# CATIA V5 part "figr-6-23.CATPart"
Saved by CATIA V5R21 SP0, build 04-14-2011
Part number: Part1
Bounding box of the stored display mesh (mm): x 0 to 150, y -70 to 70, z -150 to 69.968
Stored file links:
  D:\CATIA V5R21 E-RESOURCES\CATIA-V5R21\catia-v5r21-prt\c06-catia-v5r21-prt\c06-catia-v5r21-figr-6-23.CATPart
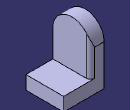
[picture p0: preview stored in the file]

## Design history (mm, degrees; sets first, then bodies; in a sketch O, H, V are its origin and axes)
Body1 (main body)
  Sketch1 on yz-plane, origin (0, 0, 0), H (0, 1, 0), V (0, 0, 1)
    arc A1 centre (0, 0) radius 70 from (70, 0) to (-70, 0) ccw
    point P1 (70, 0)
    point P2 (-70, 0)
    line L1 (-70, 0) -> (-70, -150)
    line L2 (-70, -150) -> (70, -150)
    line L3 (70, -150) -> (70, 0)
    construction circle A2 centre (0, 0) radius 37.5
    radius A1 = 70
    radius A2 = 37.5
    distance O L2 = 150
    coincidence: P1 H, P2 H
    tangency: L1 A1, L3 A1
    horizontal: L2 H
  Pad1: profile Sketch1, direction (1, 0, 0), length 50
  Sketch2 on face of Pad1, origin (50, 0, 0), H (0, 1, 0), V (0, 0, 1)
    line L1 (-70, -150) -> (70, -150)
    line L2 (70, -150) -> (70, -100)
    line L3 (70, -100) -> (-70, -100)
    line L4 (-70, -100) -> (-70, -150)
    reference projected line E1 (-70, -150) -> (70, -150) from edge [face of Pad1 | face of Pad1]
    reference projected line E2 (-70, 0) -> (-70, -150) from edge [face of Pad1 | face of Pad1]
    reference projected line E3 (70, -150) -> (70, 0) from edge [face of Pad1 | face of Pad1]
    length L2 = 50
    horizontal: L1 H, L3 H
    vertical: L2 V, L4 V
    coincidence: L1 E1, E2 L4, L2 E3
  Pad2: profile Sketch2, direction (1, 0, 0), length 100
  Fillet1: radius 15, on edge [face of Pad2 | end face of Pad1]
